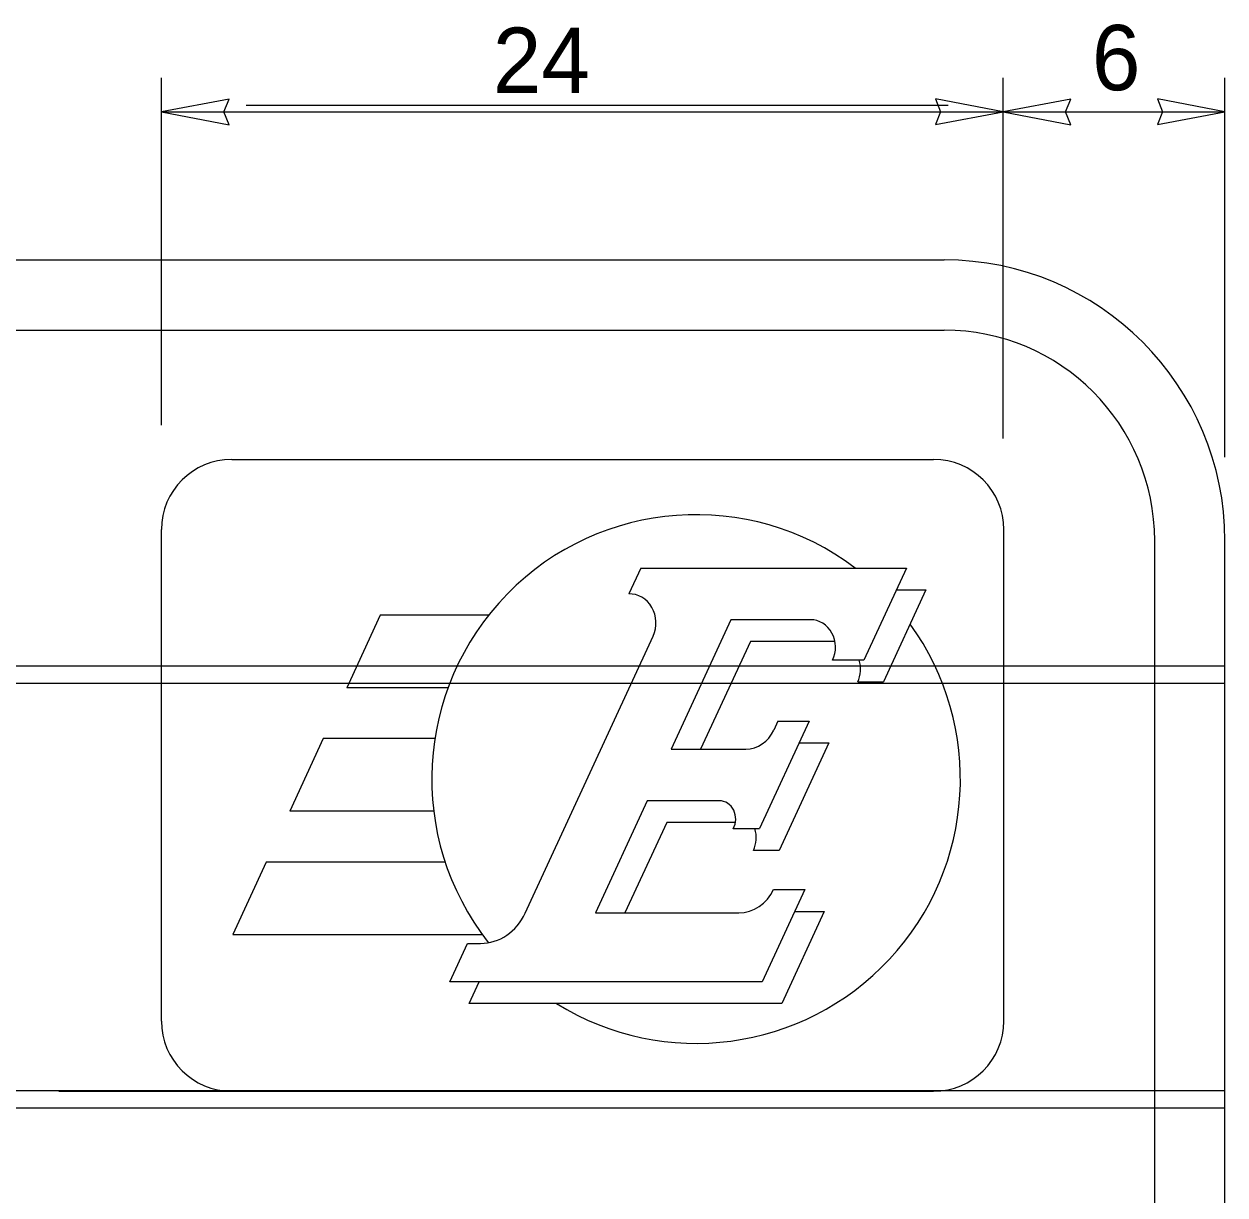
# Model space of a CAD drawing. Extents: x 319706 to 320346, y 1621790 to 1622121.
# Drawn here: x 319972.28 to 319998.04, y 1621879.28 to 1621904.4 of the extents above; entities that cross this region are included whole.
import ezdxf

# ---------------------------------------------------------------- set-up
doc = ezdxf.new("R2010")
doc.units = 0
for name, color, linetype in [('1', 7, 'Continuous'), ('52', 7, 'Continuous'), ('Default', 7, 'Continuous'), ('GSColorFill', 7, 'Continuous'), ('SignPanel', 7, 'Continuous')]:
    doc.layers.add(name, color=color, linetype=linetype)

msp = doc.modelspace()

# ---------------------------------------------------------------- linework, layer by layer
at = {"layer": '1'}
for p, q in [((319975.229, 1621895.799), (319975.229, 1621903.248)), ((319993.283, 1621895.514), (319993.283, 1621903.248)), ((319998.043, 1621895.112), (319998.043, 1621903.248)), ((319975.229, 1621902.519), (319993.283, 1621902.519)), ((319993.283, 1621902.519), (319998.043, 1621902.519))]:
    msp.add_line(p, q, dxfattribs=at)
at = {"layer": '52'}
for p, q in [((319976.679, 1621902.789), (319975.229, 1621902.519)), ((319976.569, 1621902.519), (319976.679, 1621902.789)), ((319993.283, 1621902.519), (319991.833, 1621902.799)), ((319991.833, 1621902.799), (319991.943, 1621902.519)), ((319994.733, 1621902.789), (319993.283, 1621902.519)), ((319994.623, 1621902.519), (319994.733, 1621902.789)), ((319998.043, 1621902.519), (319996.593, 1621902.799)), ((319996.593, 1621902.799), (319996.703, 1621902.519)), ((319975.229, 1621902.519), (319976.679, 1621902.239)), ((319976.679, 1621902.239), (319976.569, 1621902.519)), ((319991.943, 1621902.519), (319991.833, 1621902.249)), ((319991.833, 1621902.249), (319993.283, 1621902.519)), ((319993.283, 1621902.519), (319994.733, 1621902.239)), ((319994.733, 1621902.239), (319994.623, 1621902.519)), ((319996.703, 1621902.519), (319996.593, 1621902.249)), ((319996.593, 1621902.249), (319998.043, 1621902.519))]:
    msp.add_line(p, q, dxfattribs=at)
at = {"layer": 'Default'}
msp.add_line((319973.028, 1621881.508), (319976.735, 1621881.508), dxfattribs=at)
at = {"layer": 'GSColorFill'}
msp.add_line((319992.103, 1621902.657), (319977.044, 1621902.657), dxfattribs=at)
at = {"layer": 'SignPanel'}
for p, q in [((319895.646, 1621899.343), (319992.019, 1621899.343)), ((319895.646, 1621897.838), (319992.019, 1621897.838)), ((319976.735, 1621895.061), (319991.793, 1621895.061)), ((319975.229, 1621883.014), (319975.229, 1621893.556)), ((319993.299, 1621883.014), (319993.299, 1621893.556)), ((319996.537, 1621860.191), (319996.537, 1621893.319)), ((319998.043, 1621859.295), (319998.043, 1621893.319)), ((319985.51, 1621892.733), (319985.256, 1621892.179)), ((319985.51, 1621892.733), (319991.211, 1621892.733)), ((319991.211, 1621892.733), (319990.297, 1621890.755)), ((319991.629, 1621892.265), (319990.715, 1621890.288)), ((319990.996, 1621892.265), (319991.629, 1621892.265)), ((319979.923, 1621891.719), (319979.205, 1621890.163)), ((319982.247, 1621891.719), (319979.923, 1621891.719)), ((319987.443, 1621891.624), (319986.163, 1621888.85)), ((319989.152, 1621891.624), (319987.443, 1621891.624)), ((319983.03, 1621885.328), (319985.776, 1621891.273)), ((319987.861, 1621891.156), (319986.795, 1621888.85)), ((319989.676, 1621891.156), (319987.861, 1621891.156)), ((319889.623, 1621890.636), (319998.043, 1621890.636)), ((319990.297, 1621890.755), (319989.627, 1621890.755)), ((319889.623, 1621890.26), (319998.043, 1621890.26)), ((319981.375, 1621890.163), (319979.205, 1621890.163)), ((319990.165, 1621890.288), (319990.715, 1621890.288)), ((319989.125, 1621889.448), (319988.06, 1621887.142)), ((319988.453, 1621889.448), (319988.363, 1621889.252)), ((319988.453, 1621889.448), (319989.125, 1621889.448)), ((319978.7, 1621889.073), (319977.981, 1621887.516)), ((319981.094, 1621889.073), (319978.7, 1621889.073)), ((319986.163, 1621888.85), (319987.767, 1621888.85)), ((319989.542, 1621888.982), (319988.477, 1621886.673)), ((319988.91, 1621888.982), (319989.542, 1621888.982)), ((319981.07, 1621887.516), (319977.981, 1621887.516)), ((319985.65, 1621887.74), (319984.538, 1621885.336)), ((319987.195, 1621887.74), (319985.65, 1621887.74)), ((319986.067, 1621887.272), (319985.172, 1621885.336)), ((319987.541, 1621887.272), (319986.067, 1621887.272)), ((319987.491, 1621887.142), (319988.06, 1621887.142)), ((319988.477, 1621886.673), (319987.927, 1621886.673)), ((319977.477, 1621886.425), (319976.758, 1621884.87)), ((319981.313, 1621886.425), (319977.477, 1621886.425)), ((319989.032, 1621885.834), (319988.118, 1621883.857)), ((319988.36, 1621885.834), (319989.032, 1621885.834)), ((319984.538, 1621885.336), (319987.615, 1621885.336)), ((319989.448, 1621885.367), (319988.535, 1621883.39)), ((319988.815, 1621885.367), (319989.448, 1621885.367)), ((319976.758, 1621884.87), (319982.123, 1621884.87)), ((319981.412, 1621883.857), (319981.793, 1621884.682)), ((319981.793, 1621884.682), (319982.073, 1621884.682)), ((319988.118, 1621883.857), (319981.412, 1621883.857)), ((319981.83, 1621883.39), (319982.045, 1621883.857)), ((319988.535, 1621883.39), (319981.83, 1621883.39)), ((319889.623, 1621881.527), (319998.043, 1621881.527)), ((319976.735, 1621881.508), (319991.793, 1621881.508)), ((319889.623, 1621881.151), (319998.043, 1621881.151))]:
    msp.add_line(p, q, dxfattribs=at)
for centre, radius, start, end in [((319992.019, 1621893.319), 6.023, 0, 90), ((319992.019, 1621893.319), 4.517, 0, 90), ((319976.735, 1621893.556), 1.506, 90, 180), ((319991.793, 1621893.556), 1.506, 0, 90), ((319986.697, 1621888.207), 5.67, 52.9547, 218.1763), ((319986.697, 1621888.207), 5.67, 238.1578, 35.8999), ((319976.735, 1621883.015), 1.506, 180, 270), ((319991.793, 1621883.015), 1.506, 270, 360)]:
    msp.add_arc(centre, radius, start, end, dxfattribs=at)
for centre, major_axis, start_param, end_param in [((319985.272, 1621891.555), (0, 0.623), 4.241328, 6.314398), ((319989.152, 1621891.032), (0, 0.592), 4.227342, 6.283185), ((319989.69, 1621890.565), (0, 0.592), 4.227342, 5.041732), ((319987.766, 1621889.59), (0, 0.74), 3.141593, 4.241405), ((319987.195, 1621887.351), (0, 0.389), 4.144801, 6.283185), ((319987.452, 1621886.951), (0, 0.592), 4.227342, 5.041732), ((319987.616, 1621886.262), (0, 0.924), 3.141593, 4.232591), ((319982.074, 1621885.865), (0, 1.183), 3.141593, 4.241135)]:
    msp.add_ellipse(centre, major_axis=major_axis, ratio=0.906668, start_param=start_param, end_param=end_param, dxfattribs=at)

# ---------------------------------------------------------------- texts
at = {"layer": '1'}
for s, p in [('24', (319982.337, 1621902.925)), ('6', (319995.188, 1621902.981))]:
    msp.add_text(s, height=1.4, dxfattribs=at).set_placement(p)

doc.saveas('drawing.dxf')
